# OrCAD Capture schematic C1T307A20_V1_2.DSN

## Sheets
1 PwrStr-3V3-S3
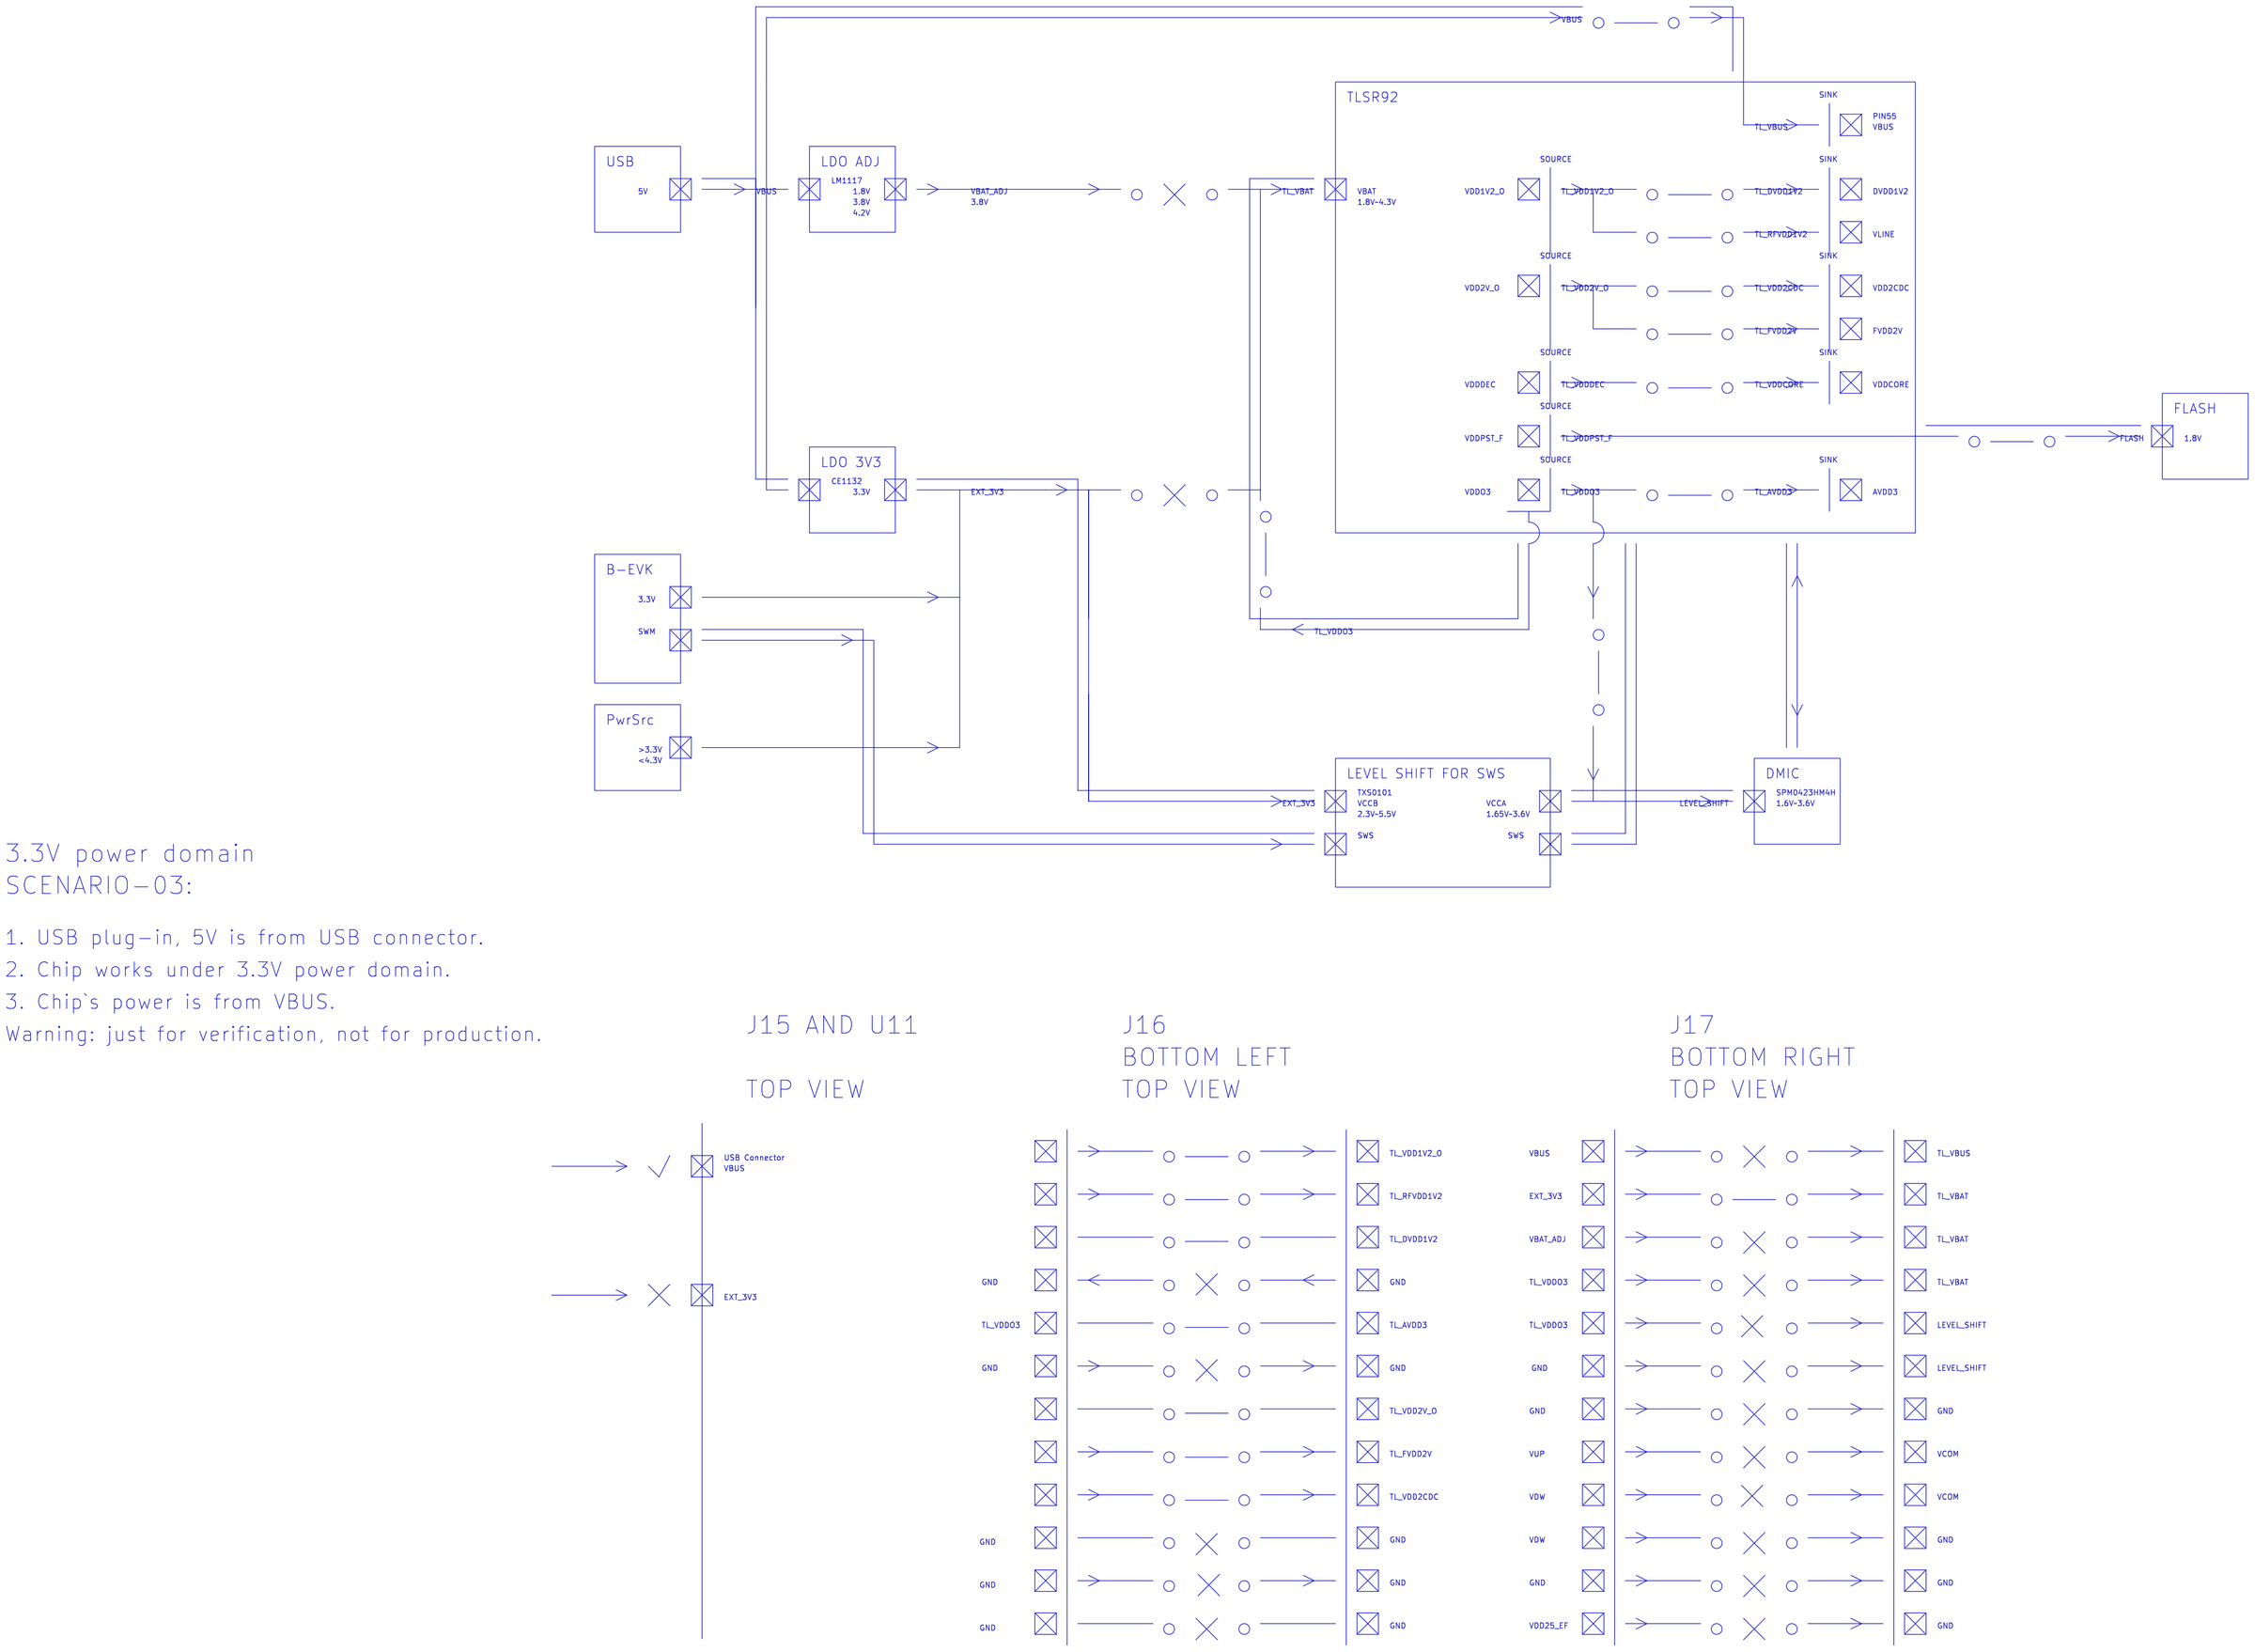
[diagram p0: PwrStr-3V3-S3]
2 PwrStr-3V3-S2
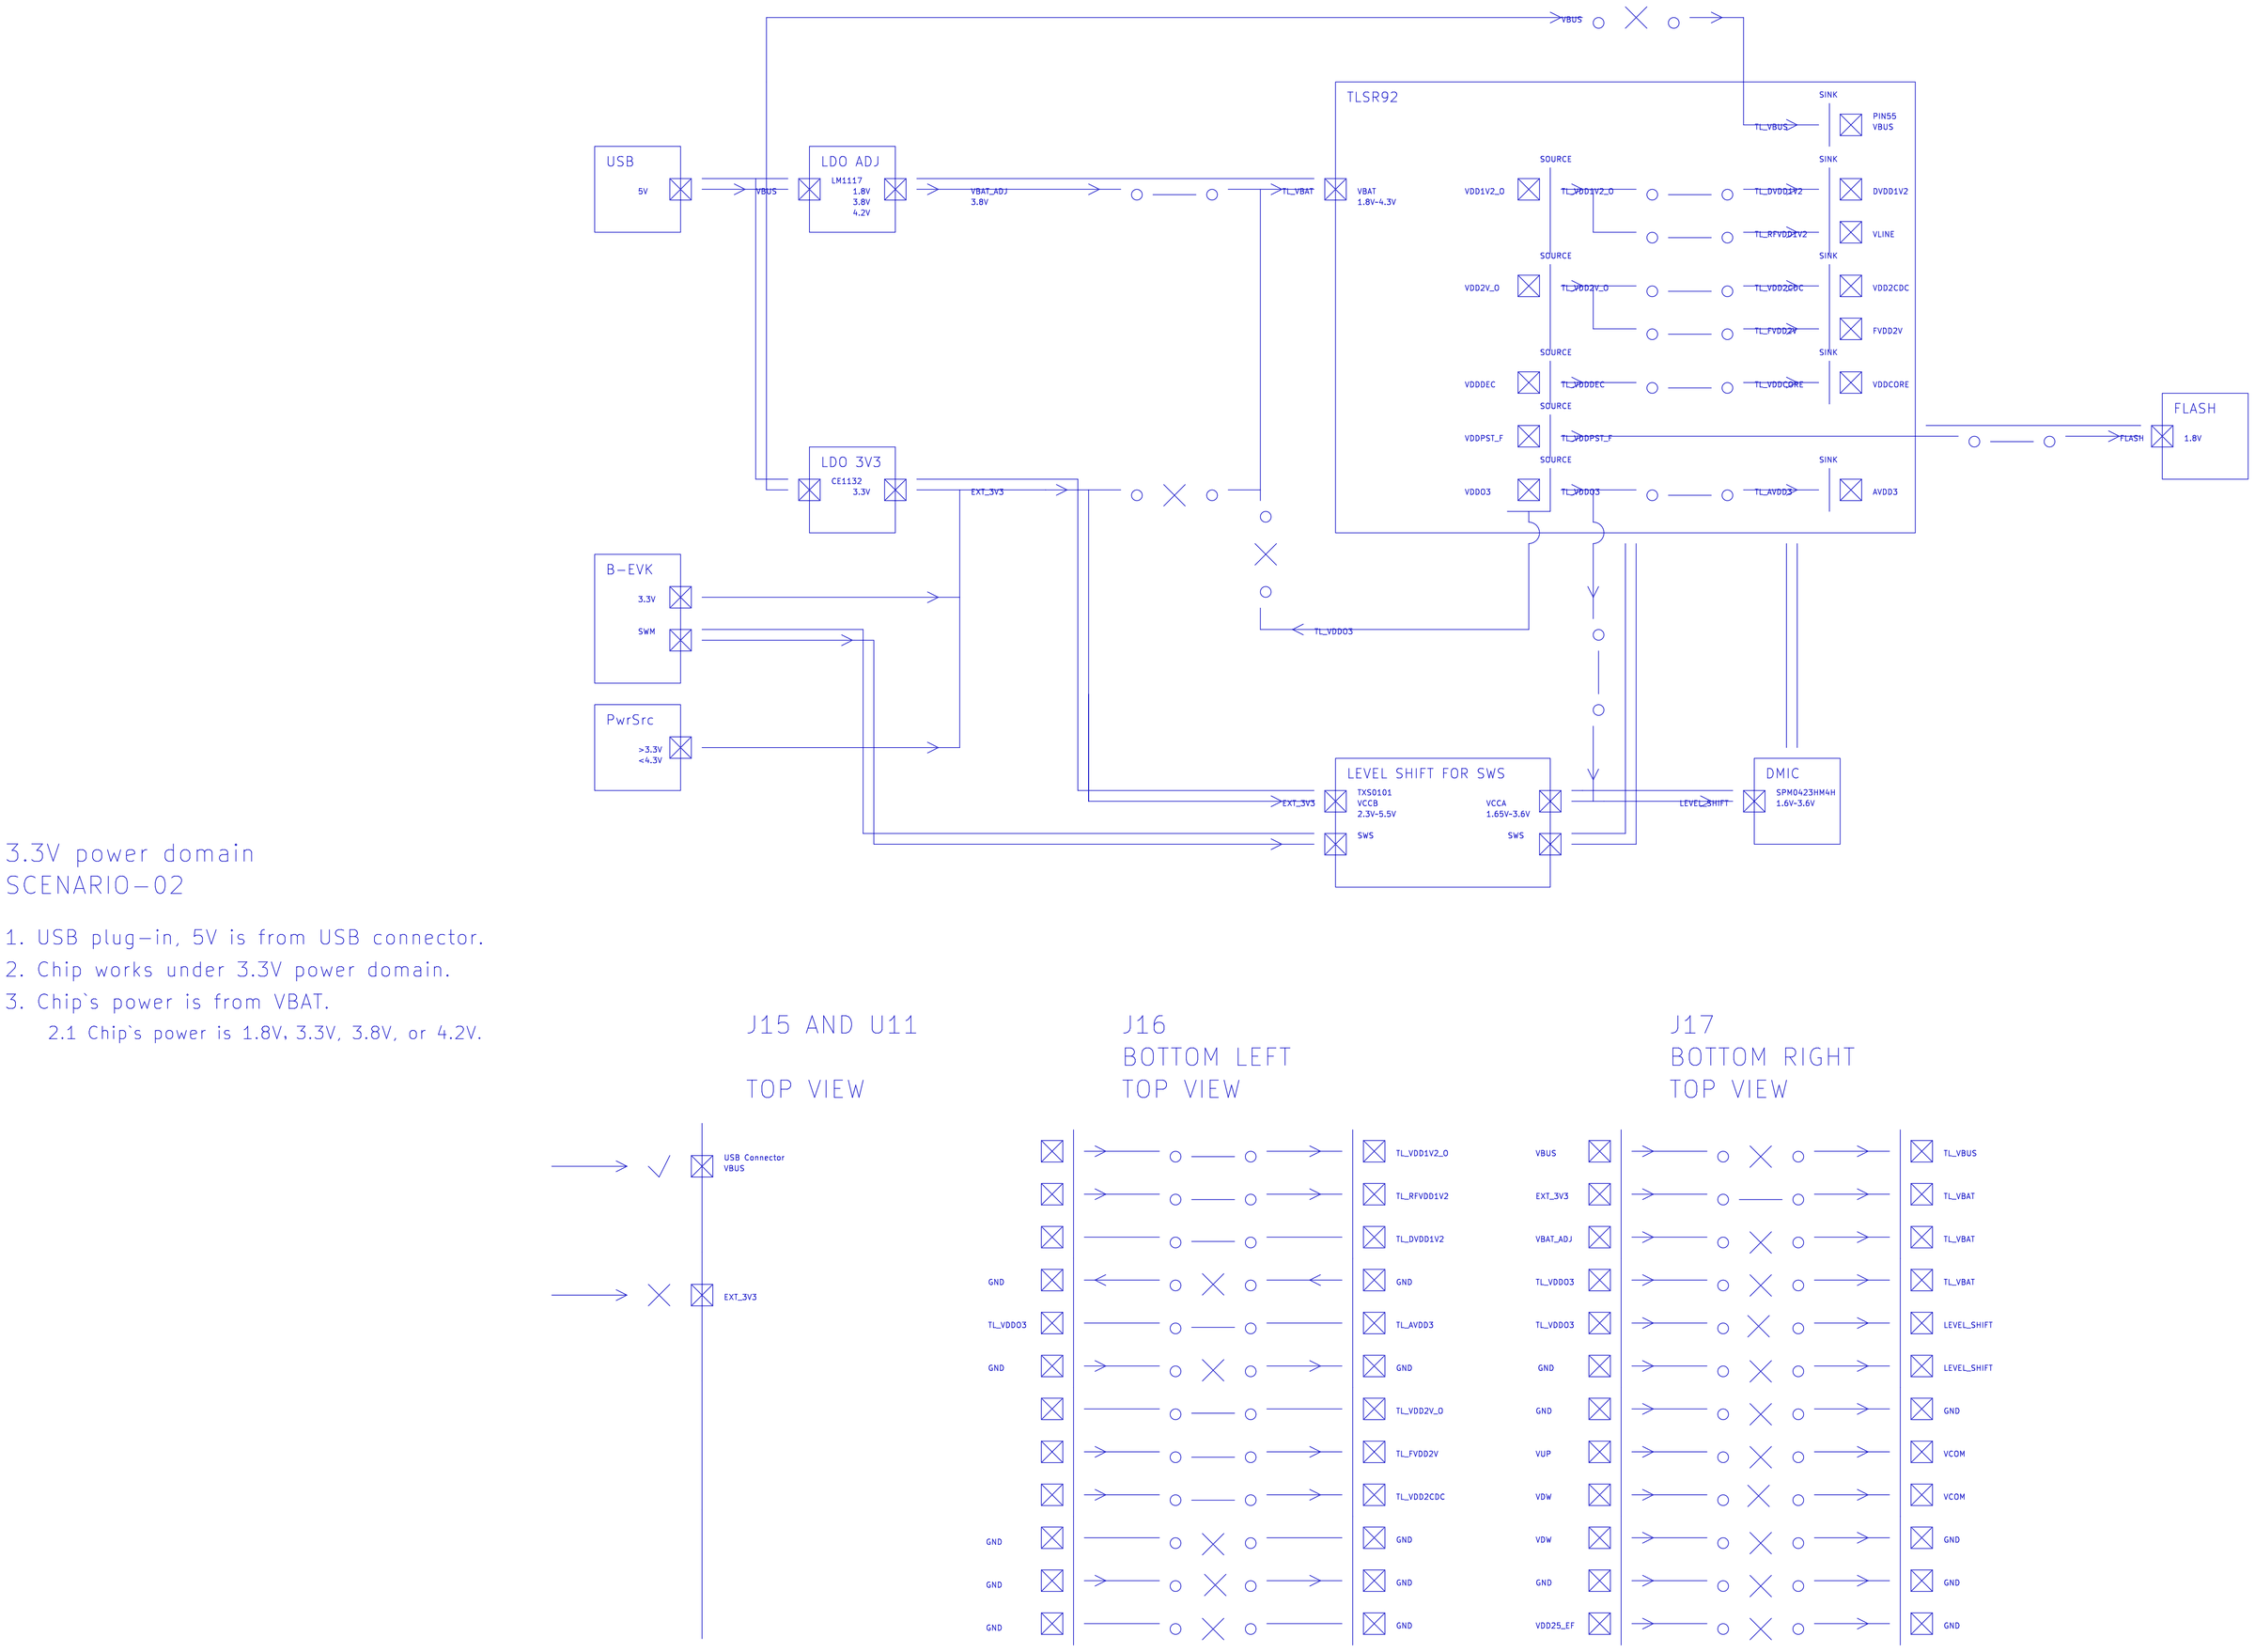
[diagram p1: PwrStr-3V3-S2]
3 PwrStr-3V3-S1
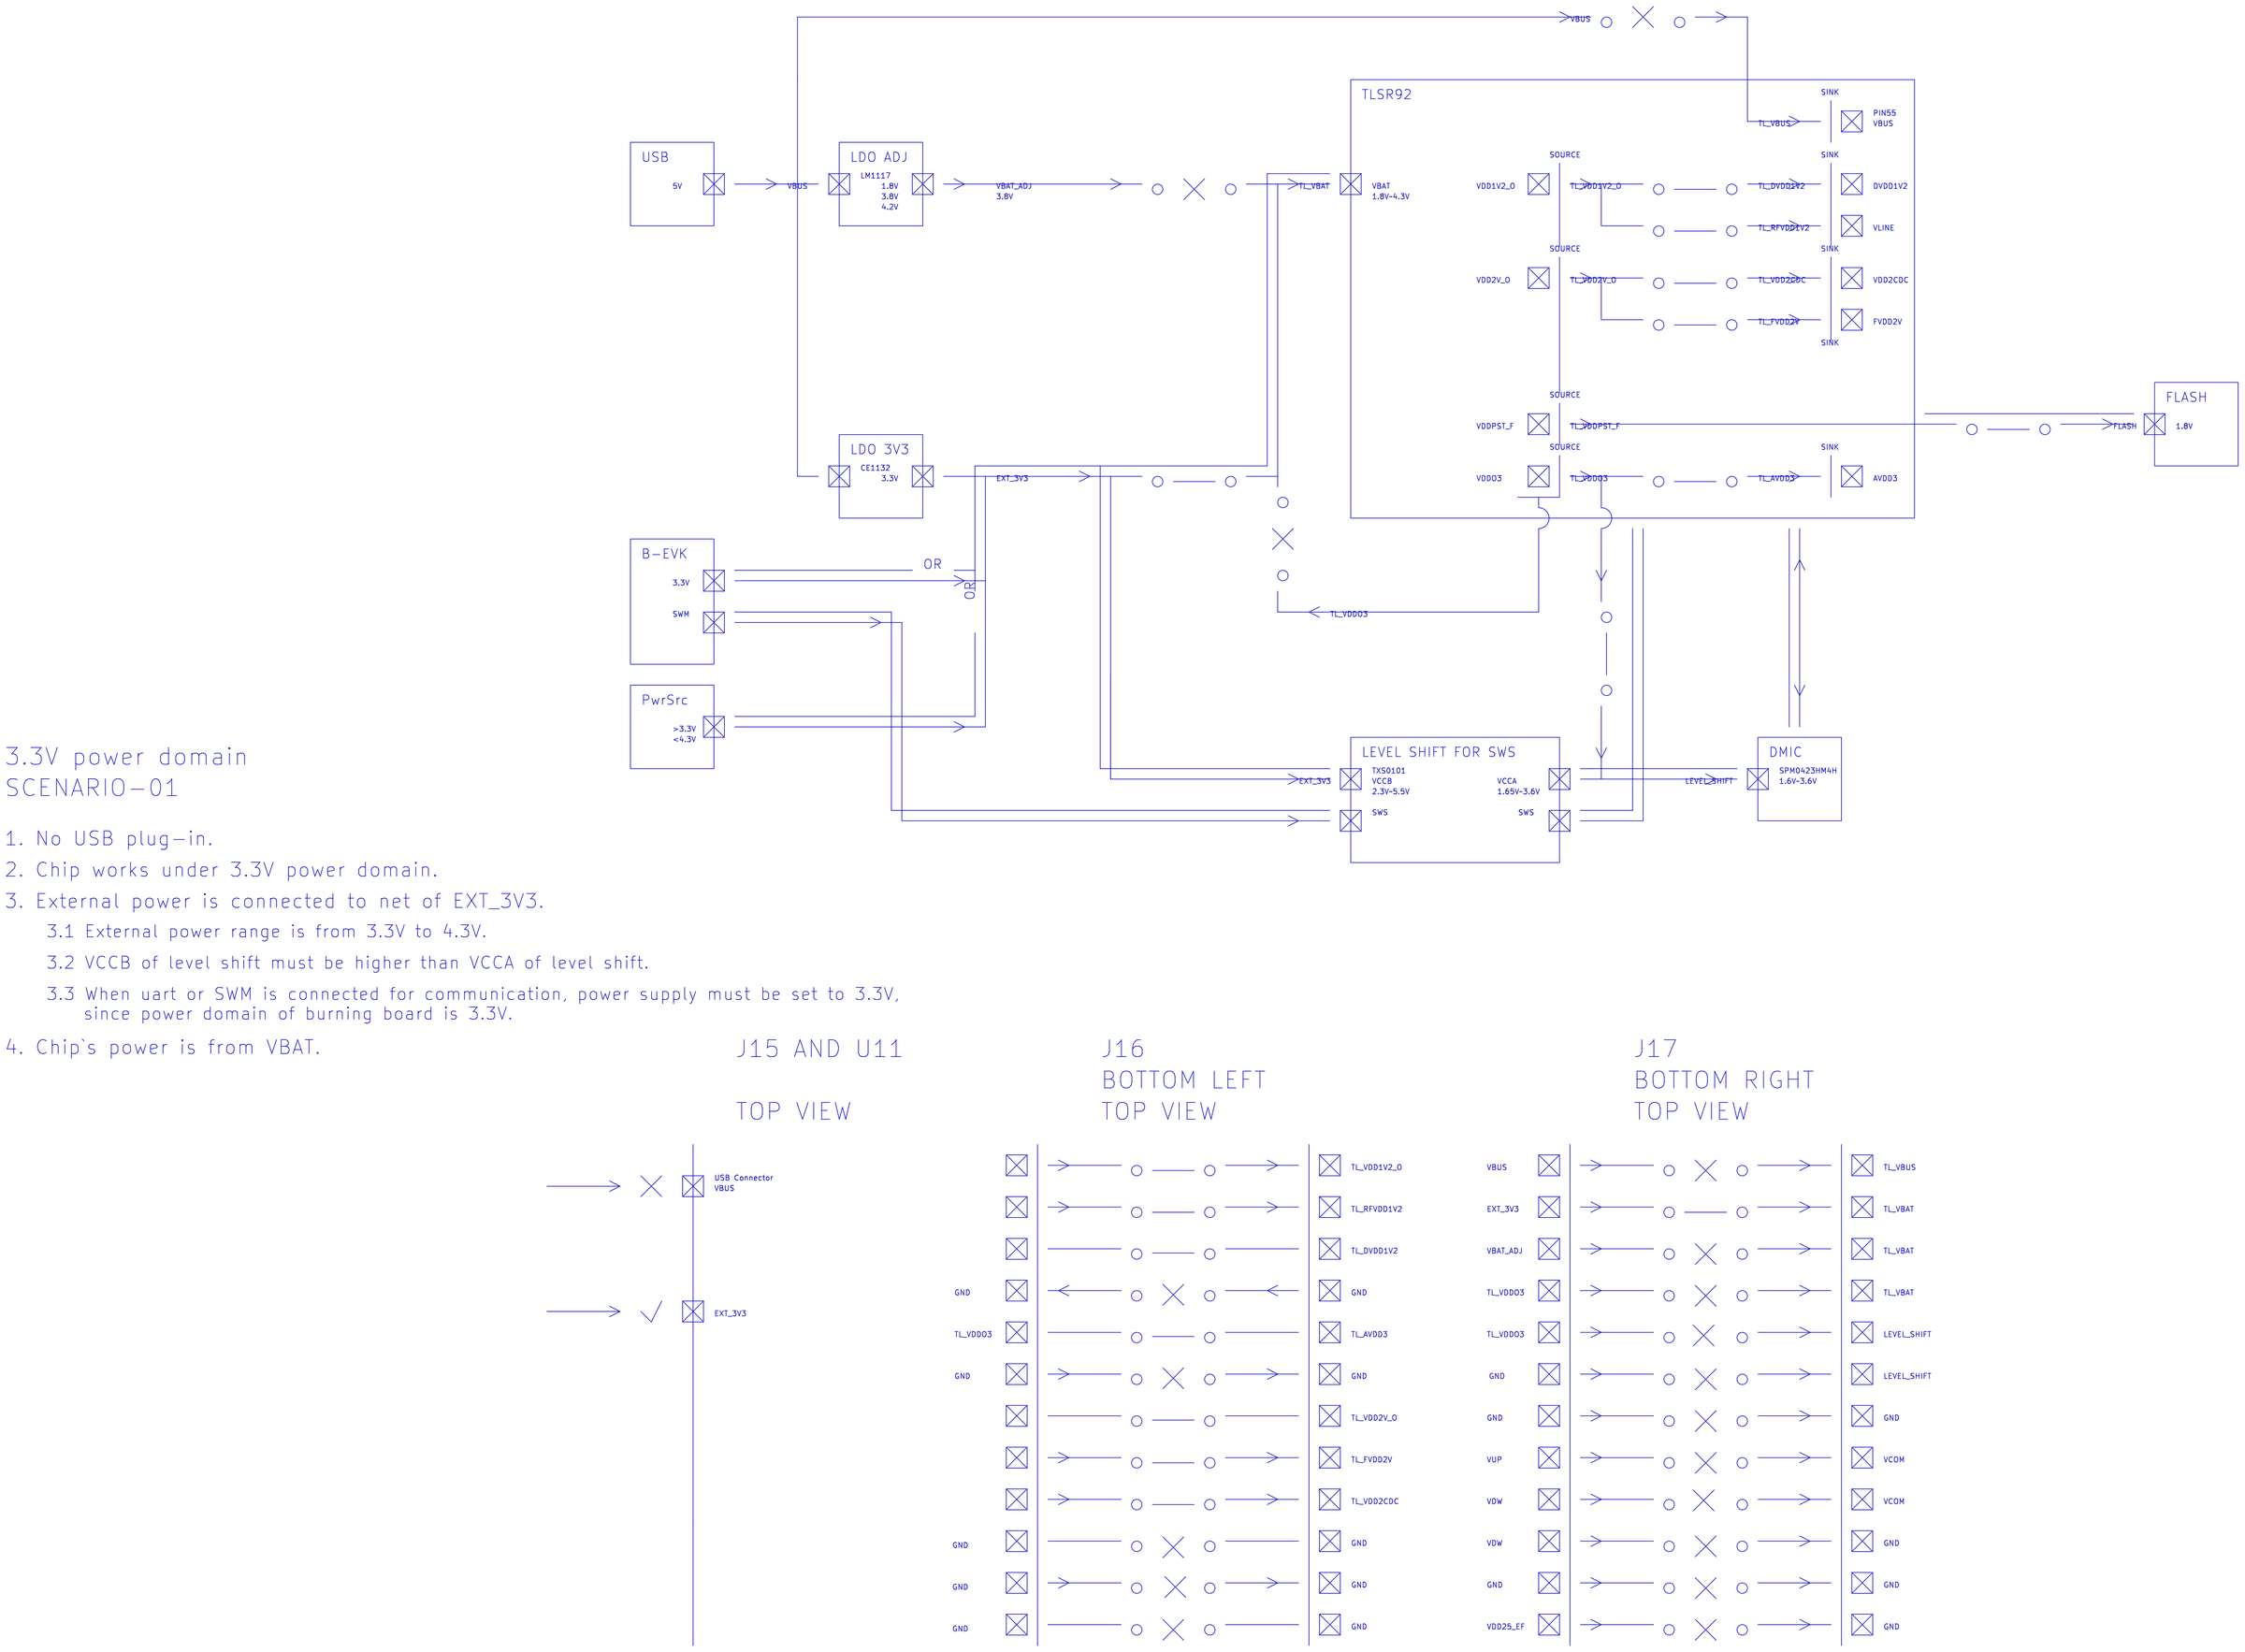
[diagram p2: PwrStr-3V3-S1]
4 000_Log: title: TELINK; rev: V1.0; note: C1T289A20
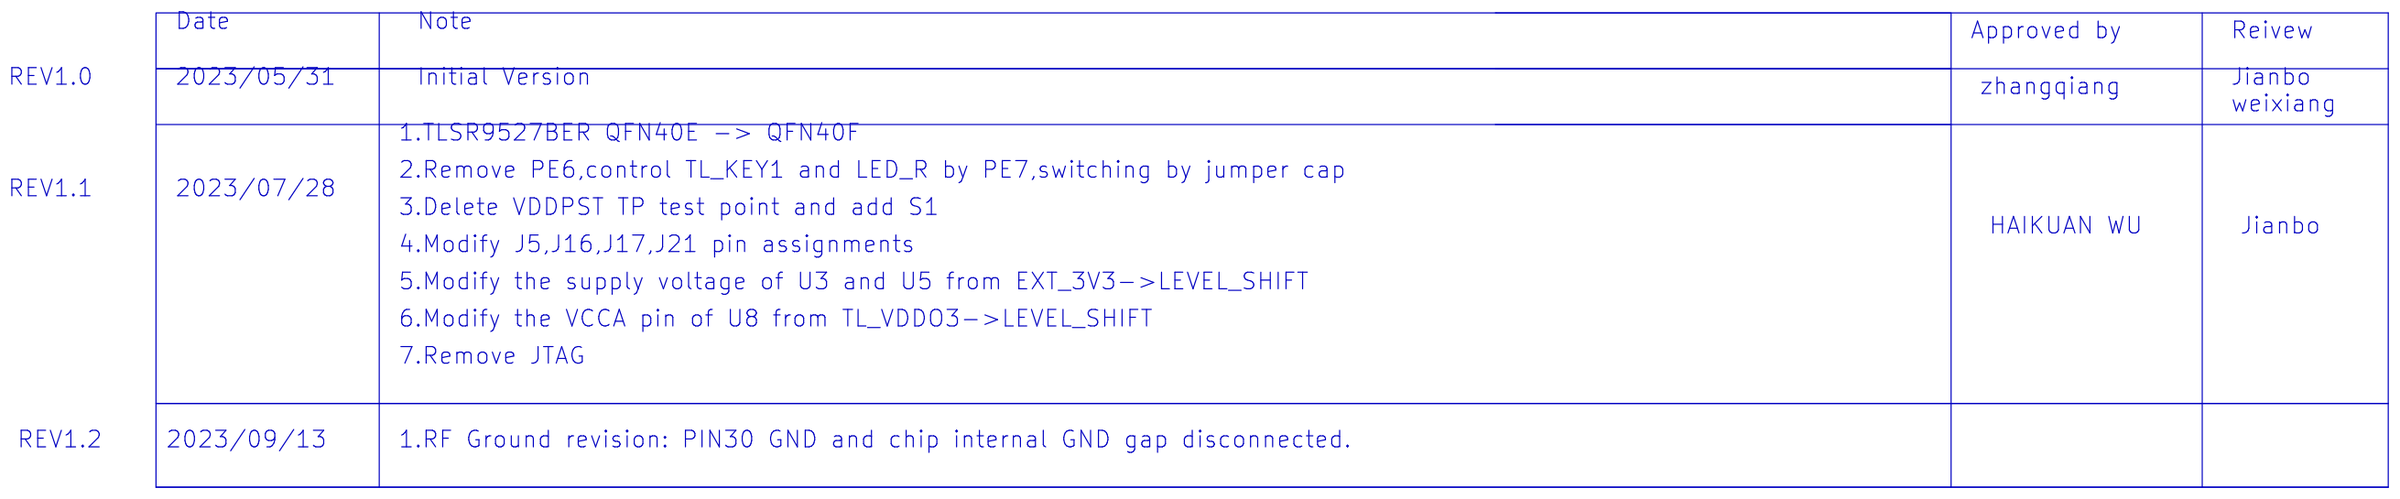
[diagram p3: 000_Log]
5 001_Structure: title: TELINK; rev: V1.1; note: C1T289A20
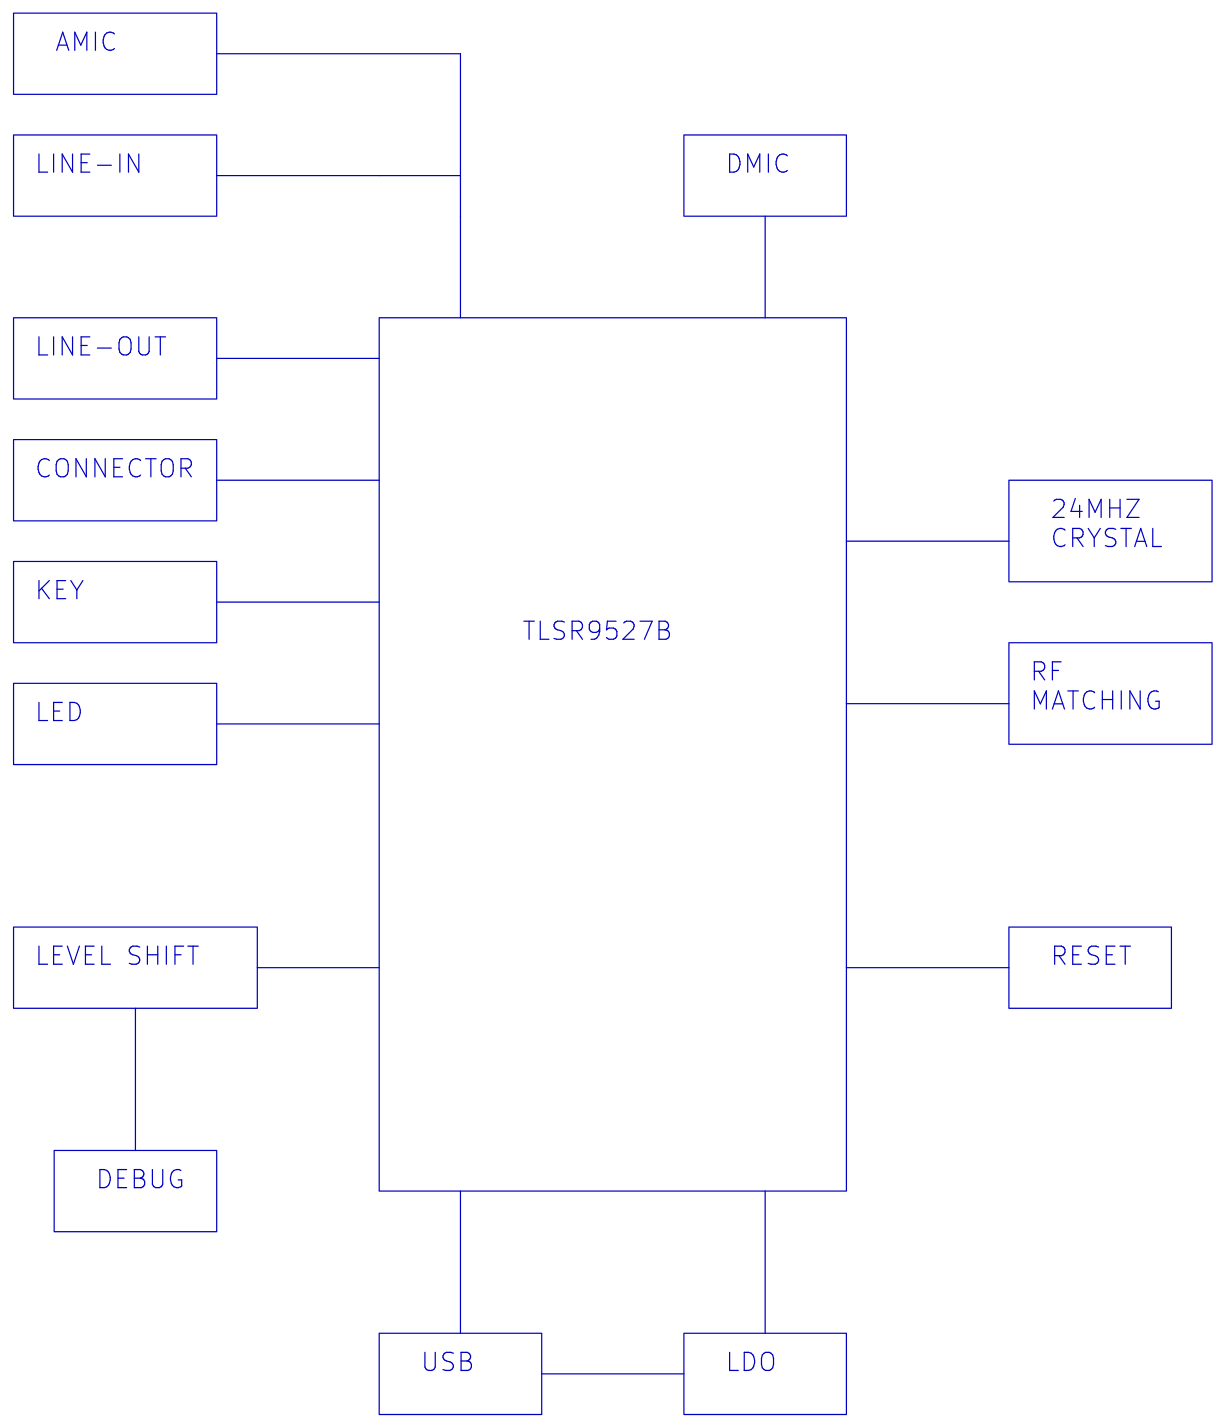
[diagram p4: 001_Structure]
6 002_MCU: size A3; title: TELINK; rev: V1.0; note: C1T289A20
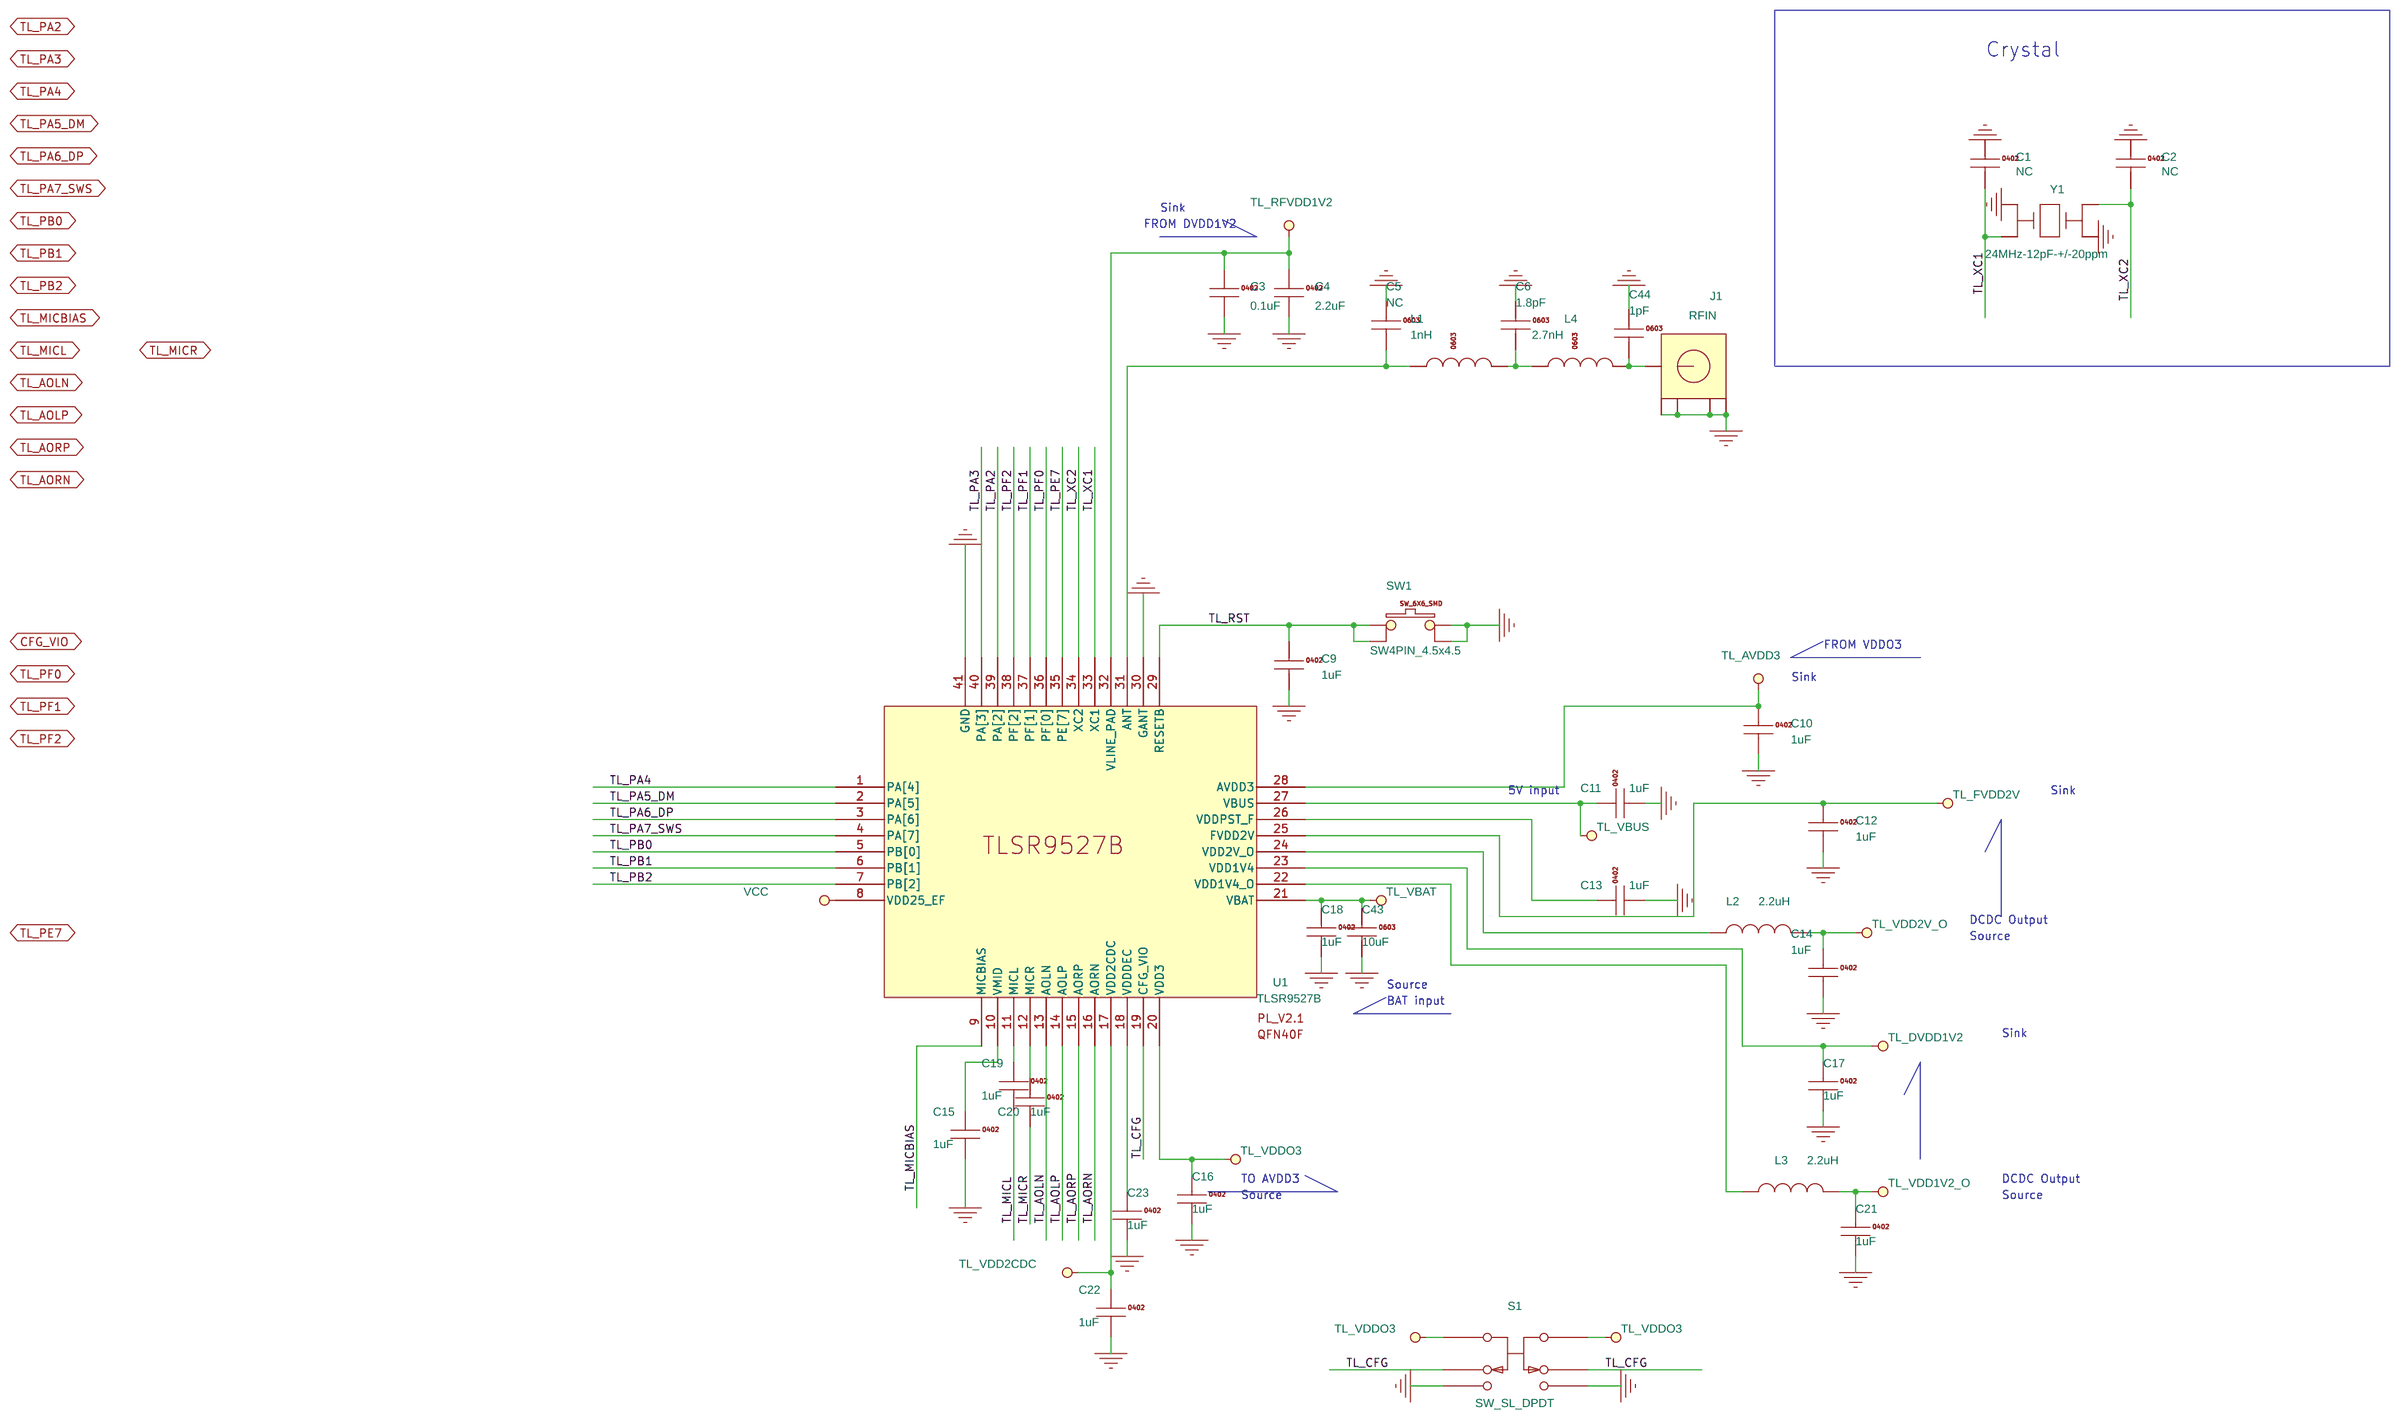
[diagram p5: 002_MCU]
7 003_INTERFACE: size A3; title: TELINK; rev: V1.0; note: C1T289A20
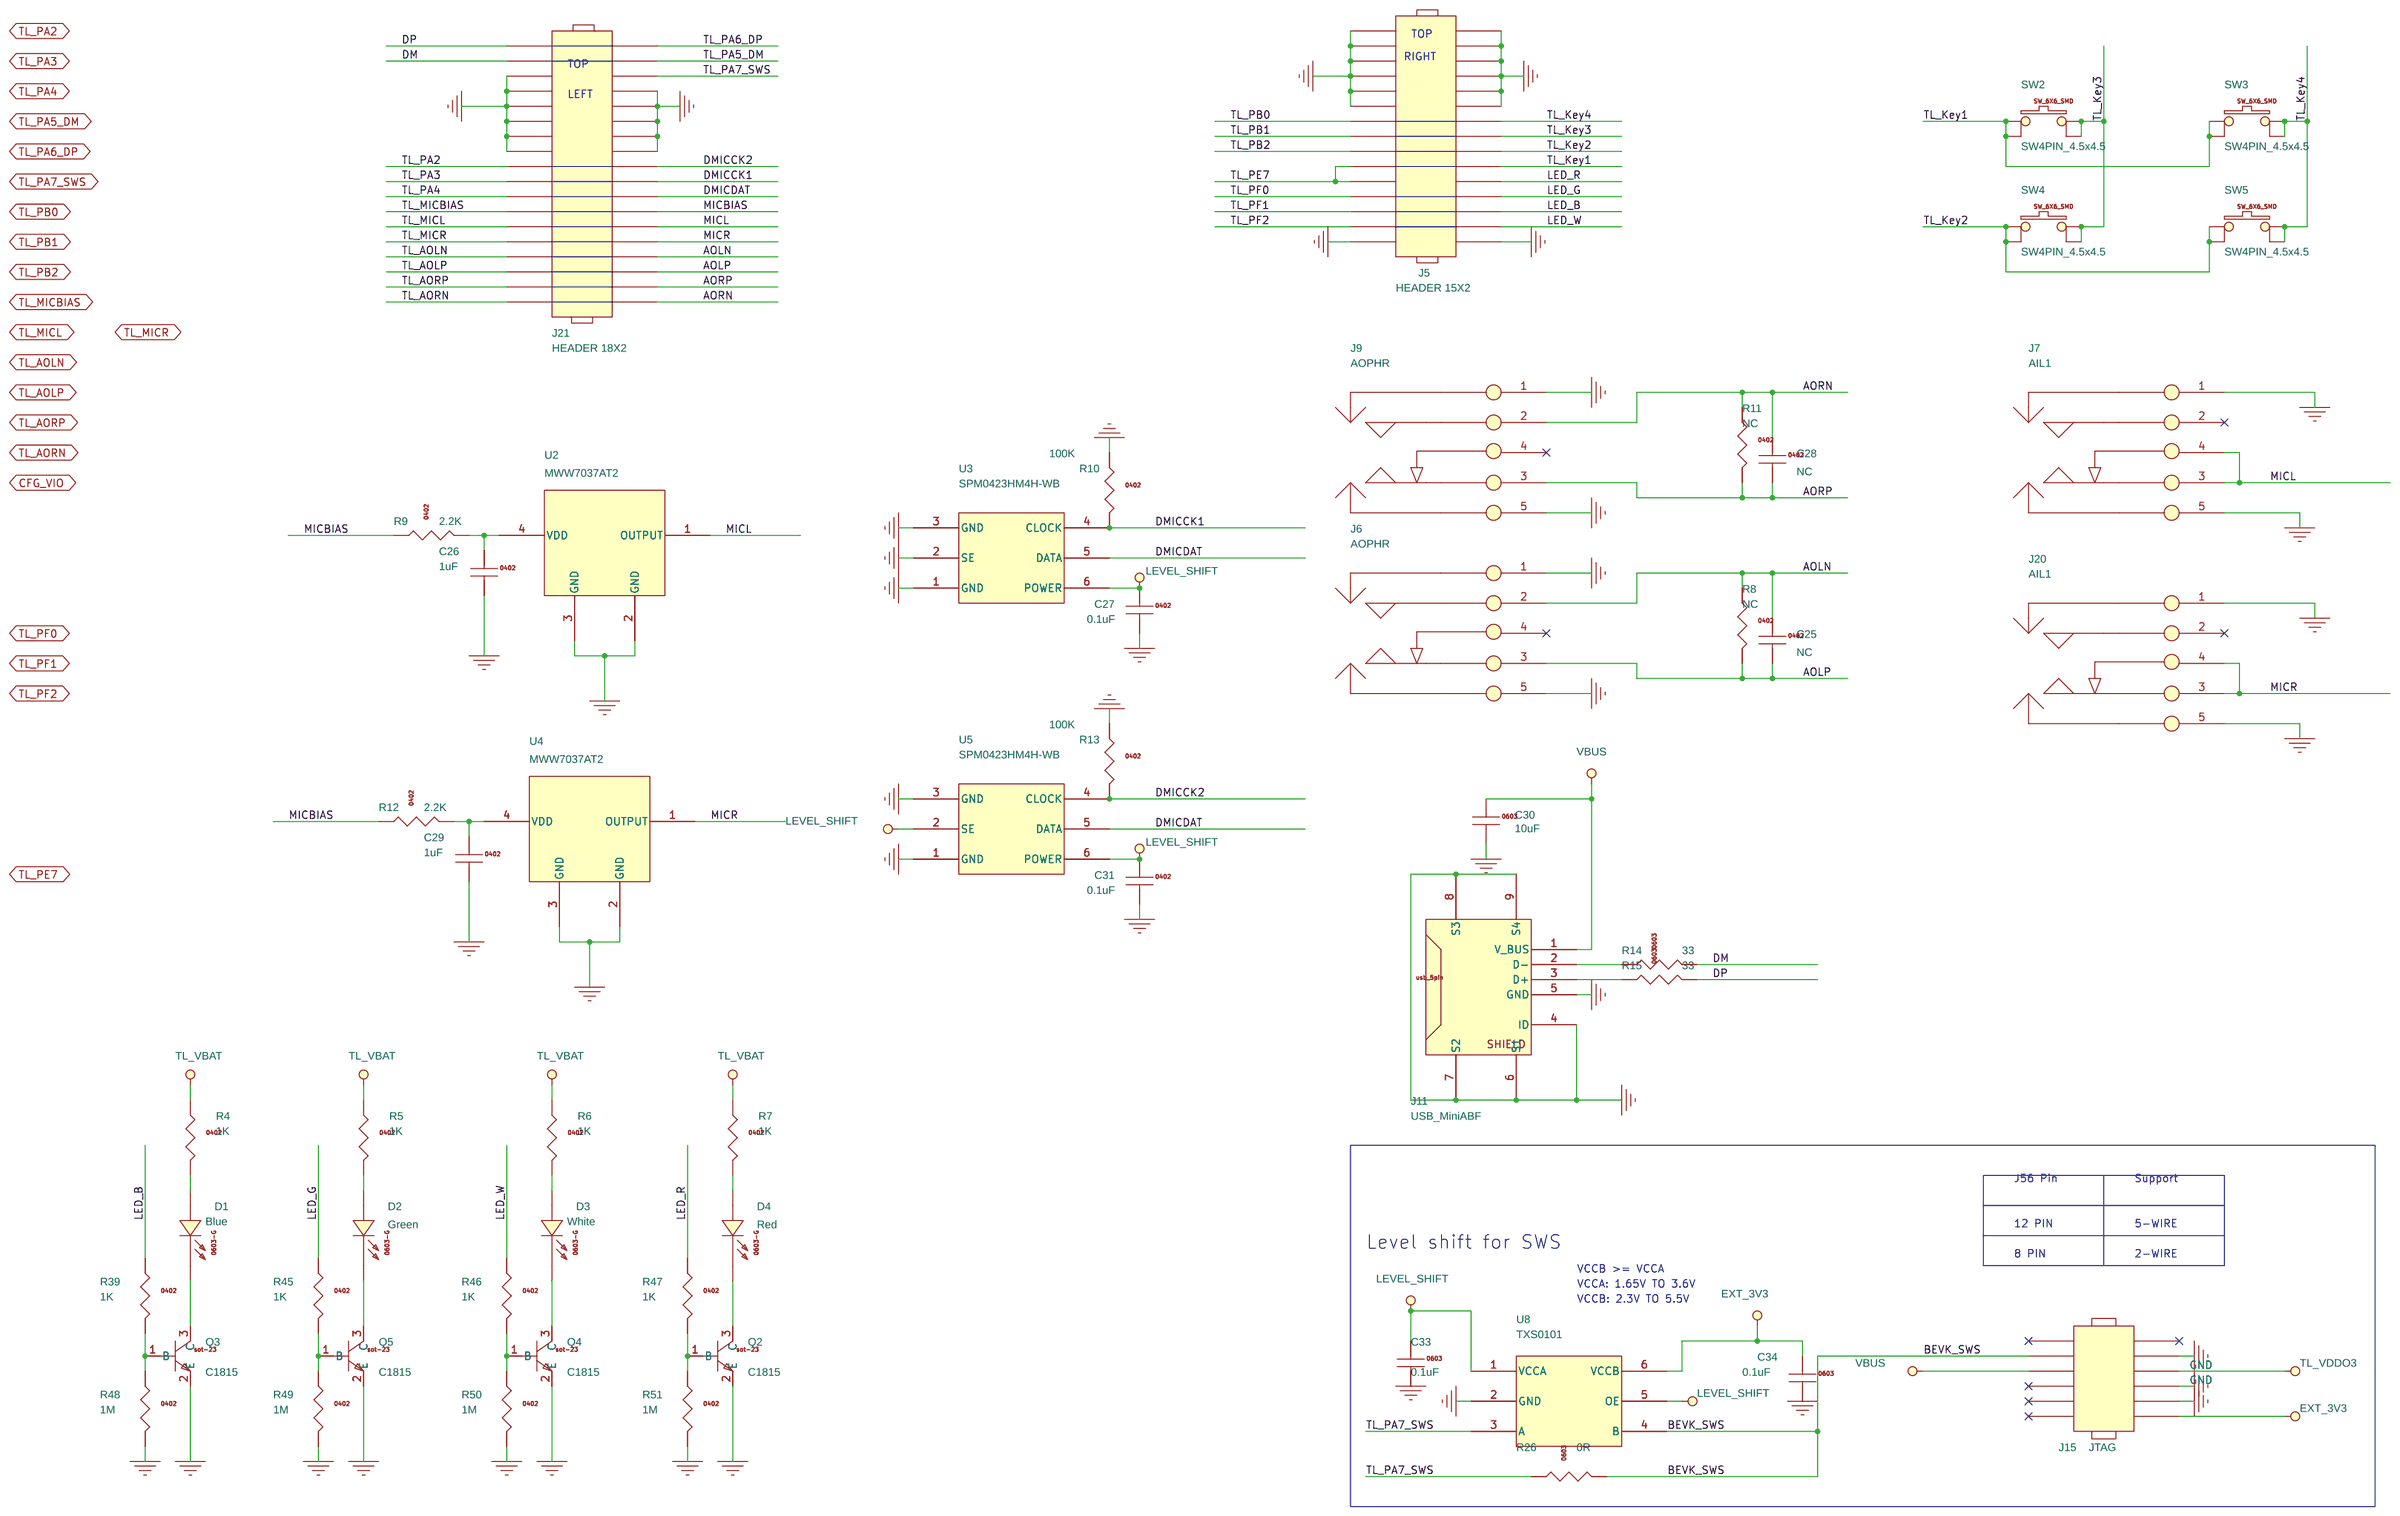
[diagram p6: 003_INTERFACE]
8 004_POWER: size A3; title: TELINK; rev: V1.0; note: C1T289A20
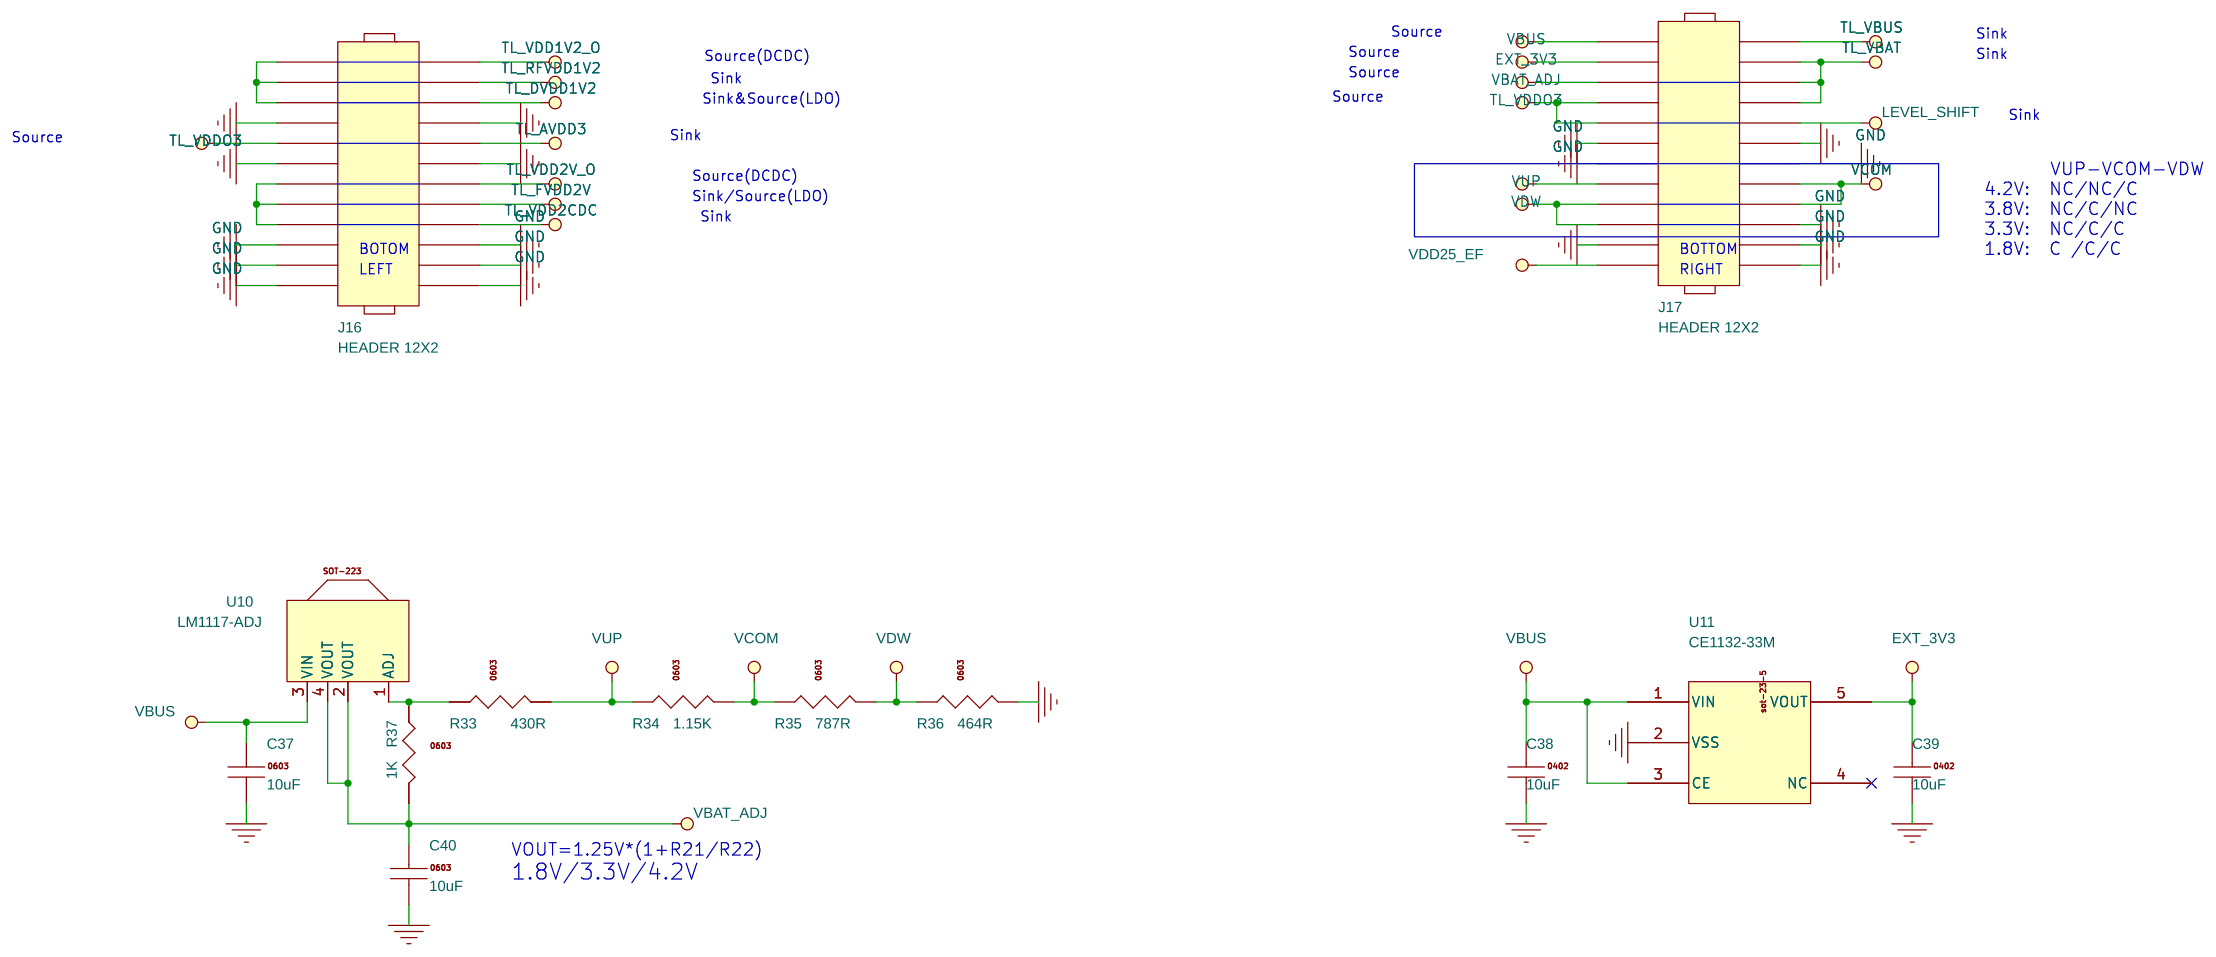
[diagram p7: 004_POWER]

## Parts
sheet 002_MCU
C1  NC  [0402]
C2  NC  [0402]
C3  0.1uF  [0402]
C4  2.2uF  [0402]
C5  NC  [0402]
C6  1.8pF  [0402]
C9  1uF  [0402]
C10  1uF  [0402]
C11  1uF  [0402]
C12  1uF  [0402]
C13  1uF  [0402]
C14  1uF  [0402]
C15  1uF  [0402]
C16  1uF  [0402]
C17  1uF  [0402]
C18  1uF  [0402]
C19  1uF  [0402]
C20  1uF  [0402]
C21  1uF  [0402]
C22  1uF  [0402]
C23  1uF  [0402]
C43  10uF  [0603C]
C44  1pF  [0402]
J1  RFIN  [SMA-H]
L1  1nH  [0402]
L2  2.2uH  [0805L]
L3  2.2uH  [0805L]
L4  2.7nH  [0402]
S1  SW_SL_DPDT  [SW-TH-6PIN-3_60X9_00-34NP]
SW1  SW4PIN_4.5x4.5  [SW_6X6_SMD]
U1  TLSR9527B  [qfn_4x6_40pin_0p4_1p10x3p10]
Y1  24MHz-12pF-+/-20ppm  [OSCCC250X320X110]
sheet 003_INTERFACE
C25  NC  [0402]
C26  1uF  [0402]
C27  0.1uF  [0402]
C28  NC  [0402]
C29  1uF  [0402]
C30  10uF  [0603C]
C31  0.1uF  [0402]
C33  0.1uF  [0402]
C34  0.1uF  [0402]
D1  Blue  [0603-LED]
D2  Green  [0603-LED]
D3  White  [0603-LED]
D4  Red  [0603-LED]
J5  HEADER 15X2  [smd254m-2x15_rx1_30y2_40]
J6  AOPHR  [PJ-327]
J7  AIL1  [PJ-327]
J9  AOPHR  [PJ-327]
J11  USB_MiniABF  [USB-MINI-F5]
J15  JTAG  [hdr254f-2x6x850]
J20  AIL1  [PJ-327]
J21  HEADER 18X2  [smd254m-2x18_rx1_30y2_40]
Q2  C1815  [SOT-23]
Q3  C1815  [SOT-23]
Q4  C1815  [SOT-23]
Q5  C1815  [SOT-23]
R4  1K  [0402]
R5  1K  [0402]
R6  1K  [0402]
R7  1K  [0402]
R8  NC  [0402]
R9  2.2K  [0402]
R10  100K  [0402]
R11  NC  [0402]
R12  2.2K  [0402]
R13  100K  [0402]
R14  33  [0402R]
R15  33  [0402R]
R26  0R  [0402R]
R39  1K  [0402]
R45  1K  [0402]
R46  1K  [0402]
R47  1K  [0402]
R48  1M  [0402]
R49  1M  [0402]
R50  1M  [0402]
R51  1M  [0402]
SW2  SW4PIN_4.5x4.5  [SW_6X6_SMD]
SW3  SW4PIN_4.5x4.5  [SW_6X6_SMD]
SW4  SW4PIN_4.5x4.5  [SW_6X6_SMD]
SW5  SW4PIN_4.5x4.5  [SW_6X6_SMD]
U2  MWW7037AT2  [ga_bfa423_a83]
U3  SPM0423HM4H-WB  [DMIC_SPM0423HM4H-WB]
U4  MWW7037AT2  [ga_bfa423_a83]
U5  SPM0423HM4H-WB  [DMIC_SPM0423HM4H-WB]
U8  TXS0101  [sc70-6]
sheet 004_POWER
C37  10uF  [0603c]
C38  10uF  [0603C]
C39  10uF  [0603C]
C40  10uF  [0603C]
J16  HEADER 12X2  [smd254m-2x12_rx1_30y2_40]
J17  HEADER 12X2  [smd254m-2x12_rx1_30y2_40]
R33  430R  [0402]
R34  1.15K  [0402]
R35  787R  [0402]
R36  464R  [0402]
R37  1K  [0402]
U10  LM1117-ADJ  [sot-223]
U11  CE1132-33M  [sot-23-5]

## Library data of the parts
C1 C2 = C1005_NC
C3 C4 C9-C23 C26 C27 C29 C31 C38 C39 = C1005X5R1C104K
C5 C6 C44 = C1608_NC
C43 = C1005X5R1C104K_0
J1 = SMA_JACK_2: PART: RF
L1 L4 = MLK1608_000R
L2 L3 = IND
S1 = SW_SL_DPDT
SW1-SW5 = SW_6X6_SMD_0
U1 = TLSR9527B
Y1 = CRYSTAL4_SM_0
C25 C28 = C1005X5R1C105K
C30 C37 = C1608X5R0J106M
C33 C34 C40 = C1608X5R1C105M
D1-D4 = 0603D_Green
J5 = HEADER_15X2
J6 J7 J9 J20 = PJ327_2
J11 = USB_MiniABF_5pin
J15 = HEADER_6X2
J21 = HEADER_18X2
Q2-Q5 = NPN_C1815
R4-R7 = RS0402K102JT
R8-R13 = RS0402K104JT
R14 R15 = RS0603K330JT
R26 = RS0603K102JT
R39 R45-R51 = RS0402K101JT
U2 U4 = MULPS4CX-RM5_0
U3 U5 = LD1117_SO_0
U8 = TXS0101
J16 J17 = HEADER_12X2
R33-R37 = RS0603K104JT
U10 = XC62FP3302_0.3V_SOT-89
U11 = XC6219_6.3V_SOT-23-5

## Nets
GND: C1.1 C2.1 C3.2 C4.2 C5.1 C6.1 C9.2 C10.2 C11.2 C12.2 C13.2 C14.2 C15.2 C16.2 C17.2 C18.2 C21.2 C22.2 C23.2 C26.2 C27.2 C29.2 C30.2 C31.2 C33.2 C34.2 C37.2 C38.2 C39.2 C40.2 C43.2 C44.1 J1.2 J1.3 J1.4 J1.5 J5.1 J5.2 J5.3 J5.4 J5.5 J5.6 J5.7 J5.8 J5.9 J5.10 J5.11 J5.12 J5.29 J5.30 J6.1 J6.5 J7.1 J7.5 J9.1 J9.5 J11.4(ID) J11.5(GND) J11.6(S1) J11.7(S2) J11.8(S3) J11.9(S4) J15.3 J15.5 J15.9 J16.7 J16.8 J16.11 J16.12 J16.19 J16.20 J16.21 J16.22 J16.23 J16.24 J17.11 J17.12 J17.13 J17.14 J17.19 J17.21 J17.22 J17.23 J20.1 J20.5 J21.6 J21.7 J21.8 J21.9 J21.10 J21.11 J21.12 J21.13 J21.14 J21.15 J21.16 Q2.2(E) Q3.2(E) Q4.2(E) Q5.2(E) R10.1 R13.1 R36.2 R48.2 R49.2 R50.2 R51.2 S1.3 S1.4 SW1.3 SW1.4 U1.30(GANT) U1.41(GND) U2.2(GND) U2.3(GND) U3.1(GND) U3.2(SE) U3.3(GND) U4.2(GND) U4.3(GND) U5.1(GND) U5.3(GND) U8.2(GND) U11.2(VSS) Y1.2 Y1.4
VBAT_ADJ: C40.1 J17.6 R37.2 U10.2(VOUT) U10.4(VOUT)
VBUS: C30.1 C37.1 C38.1 J11.1(V_BUS) J15.8 J17.2 U10.3(VIN) U11.1(VIN) U11.3(CE)
VDD25_EF: J17.24 U1.8(VDD25_EF)
AOLN: C25.1 J6.2 J21.29 R8.1
AOLP: C25.2 J6.3 J21.31 R8.2
AORN: C28.1 J9.2 J21.35 R11.1
AORP: C28.2 J9.3 J21.33 R11.2
BEVK_SWS: J15.10 R26.2 U8.4(B)
DM: J21.4 R14.2
DMICCK1: J21.19 R10.2 U3.4(CLOCK)
DMICCK2: J21.17 R13.2 U5.4(CLOCK)
DMICDAT: J21.21 U3.5(DATA) U5.5(DATA)
DP: J21.2 R15.2
EXT_3V3: C34.1 C39.1 J15.1 J17.4 U8.6(VCCB) U11.5(VOUT)
LED_B: J5.25 R39.1
LED_G: J5.23 R45.1
LED_R: J5.21 R47.1
LED_W: J5.27 R46.1
LEVEL_SHIFT: C27.1 C31.1 C33.1 J17.9 U3.6(POWER) U5.2(SE) U5.6(POWER) U8.1(VCCA) U8.5(OE)
MICBIAS: J21.23 R9.1 R12.1
MICL: J7.3 J7.4 J21.25 U2.1(OUTPUT)
MICR: J20.3 J20.4 J21.27 U4.1(OUTPUT)
TL_AOLN: U1.13(AOLN)
TL_AOLN (page 003_INTERFACE): J21.30
TL_AOLP: U1.14(AOLP)
TL_AOLP (page 003_INTERFACE): J21.32
TL_AORN: U1.16(AORN)
TL_AORN (page 003_INTERFACE): J21.36
TL_AORP: U1.15(AORP)
TL_AORP (page 003_INTERFACE): J21.34
TL_AVDD3: C10.1 J16.9 U1.28(AVDD3)
TL_CFG: S1.2 S1.5 U1.19(CFG_VIO)
TL_DVDD1V2: C17.1 J16.5 U1.23(VDD1V4)
TL_FVDD2V: C12.1 J16.15 U1.25(FVDD2V)
TL_Key1: J5.19 SW2.1 SW2.2 SW3.1 SW3.2
TL_Key2: J5.17 SW4.1 SW4.2 SW5.1 SW5.2
TL_Key3: J5.15 SW2.3 SW2.4 SW4.3 SW4.4
TL_Key4: J5.13 SW3.3 SW3.4 SW5.3 SW5.4
TL_MICBIAS: U1.9(MICBIAS)
TL_MICBIAS (page 003_INTERFACE): J21.24
TL_MICL: C19.2
TL_MICL (page 003_INTERFACE): J21.26
TL_MICR: C20.2
TL_MICR (page 003_INTERFACE): J21.28
TL_PA2: U1.39(PA[2])
TL_PA2 (page 003_INTERFACE): J21.18
TL_PA3: U1.40(PA[3])
TL_PA3 (page 003_INTERFACE): J21.20
TL_PA4: U1.1(PA[4])
TL_PA4 (page 003_INTERFACE): J21.22
TL_PA5_DM: U1.2(PA[5])
TL_PA5_DM (page 003_INTERFACE): J21.3
TL_PA6_DP: U1.3(PA[6])
TL_PA6_DP (page 003_INTERFACE): J21.1
TL_PA7_SWS: U1.4(PA[7])
TL_PA7_SWS (page 003_INTERFACE): J21.5 R26.1 U8.3(A)
TL_PB0: U1.5(PB[0])
TL_PB0 (page 003_INTERFACE): J5.14
TL_PB1: U1.6(PB[1])
TL_PB1 (page 003_INTERFACE): J5.16
TL_PB2: U1.7(PB[2])
TL_PB2 (page 003_INTERFACE): J5.18
TL_PE7: U1.35(PE[7])
TL_PE7 (page 003_INTERFACE): J5.20 J5.22
TL_PF0: U1.36(PF[0])
TL_PF0 (page 003_INTERFACE): J5.24
TL_PF1: U1.37(PF[1])
TL_PF1 (page 003_INTERFACE): J5.26
TL_PF2: U1.38(PF[2])
TL_PF2 (page 003_INTERFACE): J5.28
TL_RFVDD1V2: C3.1 C4.1 J16.3 U1.32(VLINE_PAD)
TL_RST: C9.1 SW1.1 SW1.2 U1.29(RESETB)
TL_VBAT: C18.1 C43.1 J17.3 J17.5 J17.7 R4.1 R5.1 R6.1 R7.1 U1.21(VBAT)
TL_VBUS: C11.1 J17.1 U1.27(VBUS)
TL_VDD1V2_O: C21.1 J16.1 L3.2
TL_VDD2CDC: C22.1 J16.17 U1.17(VDD2CDC)
TL_VDD2V_O: C14.1 J16.13 L2.2
TL_VDDO3: C16.1 J15.7 J16.10 J17.8 J17.10 S1.1 S1.6 U1.20(VDD3)
TL_XC1: C1.2 U1.33(XC1) Y1.3
TL_XC2: C2.2 U1.34(XC2) Y1.1
VCOM: J17.15 J17.17 R34.2 R35.1
VDW: J17.18 J17.20 R35.2 R36.1
VUP: J17.16 R33.2 R34.1
N20028206: R33.1 R37.1 U10.1(ADJ)
N20031278: C15.1 U1.10(VMID)
N20031514: C5.2 L1.1 U1.31(ANT)
N20035363: C26.1 R9.2 U2.4(VDD)
N20050417: J11.3(D+) R15.1
N20050429: J11.2(D-) R14.1
N20122497: L2.1 U1.24(VDD2V_O)
N20122505: L3.1 U1.22(VDD1V4_O)
N20122726: C13.1 U1.26(VDDPST_F)
N20123815: C29.1 R12.2 U4.4(VDD)
N20128470: D4.C(CATHODE) Q2.3(C)
N20128482: Q2.1(B) R47.2 R51.1
N20128486: D4.A(ANODE) R7.2
N20128502: D1.C(CATHODE) Q3.3(C)
N20128524: Q3.1(B) R39.2 R48.1
N20128528: D1.A(ANODE) R4.2
N20128530: D3.C(CATHODE) Q4.3(C)
N20128552: Q4.1(B) R46.2 R50.1
N20128556: D3.A(ANODE) R6.2
N20128560: D2.C(CATHODE) Q5.3(C)
N20128580: Q5.1(B) R45.2 R49.1
N20128584: D2.A(ANODE) R5.2
N20160217: C23.1 U1.18(VDDDEC)
N20160455: C20.1 U1.12(MICR)
N20160512: C19.1 U1.11(MICL)
N20164995: C44.2 J1.1 L4.2
N20165028: C6.2 L1.2 L4.1
N20174575: J16.2 J16.4 J16.6
N20174708: J16.14 J16.16 J16.18

Not connected (* = marked no-connect by the designer): J6 4*; J7 2*; J9 4*; J15 2* 4* 6* 11* 12*; J20 2*; U11 4(NC)*

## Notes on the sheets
sheet 1
- VBUS
- TLSR92
- SINK
- TL_VBUS
- PIN55
- VBUS
- USB
- LDO ADJ
- SOURCE
- SINK
- 5V
- VBUS
- LM1117
- 1.8V
- VBAT_ADJ
- TL_VBAT
- VBAT
- VDD1V2_O
- TL_VDD1V2_O
- TL_DVDD1V2
- DVDD1V2
- 3.8V
- 3.8V
- 1.8V~4.3V
- 4.2V
- TL_RFVDD1V2
- VLINE
- SOURCE
- SINK
- VDD2V_O
- TL_VDD2V_O
- TL_VDD2CDC
- VDD2CDC
- TL_FVDD2V
- FVDD2V
- SOURCE
- SINK
- VDDDEC
- TL_VDDDEC
- TL_VDDCORE
- VDDCORE
- SOURCE
- FLASH
- VDDPST_F
- TL_VDDPST_F
- FLASH
- 1.8V
- LDO 3V3
- SOURCE
- SINK
- CE1132
- 3.3V
- EXT_3V3
- VDDO3
- TL_VDDO3
- TL_AVDD3
- AVDD3
- B-EVK
- 3.3V
- SWM
- TL_VDDO3
- PwrSrc
- <4.3V
- >3.3V
- LEVEL SHIFT FOR SWS
- DMIC
- TXS0101
- SPM0423HM4H
- EXT_3V3
- VCCB
- VCCA
- LEVEL_SHIFT
- 1.6V~3.6V
- 2.3V~5.5V
- 1.65V~3.6V
- SWS
- SWS
- 3.3V power domain
- SCENARIO-03:
- 1. USB plug-in, 5V is from USB connector.
- 2. Chip works under 3.3V power domain.
- 3. Chip`s power is from VBUS.
- J15 AND U11
- J16
- J17
- Warning: just for verification, not for production.
- BOTTOM LEFT
- BOTTOM RIGHT
- TOP VIEW
- TOP VIEW
- TOP VIEW
- TL_VDD1V2_O
- VBUS
- TL_VBUS
- USB Connector
- VBUS
- TL_RFVDD1V2
- EXT_3V3
- TL_VBAT
- TL_DVDD1V2
- VBAT_ADJ
- TL_VBAT
- GND
- GND
- TL_VDDO3
- TL_VBAT
- EXT_3V3
- TL_VDDO3
- TL_AVDD3
- TL_VDDO3
- LEVEL_SHIFT
- GND
- GND
- GND
- LEVEL_SHIFT
- TL_VDD2V_O
- GND
- GND
- TL_FVDD2V
- VUP
- VCOM
- TL_VDD2CDC
- VDW
- VCOM
- GND
- GND
- VDW
- GND
- GND
- GND
- GND
- GND
- GND
- GND
- VDD25_EF
- GND
sheet 2
- VBUS
- TLSR92
- SINK
- TL_VBUS
- PIN55
- VBUS
- USB
- LDO ADJ
- SOURCE
- SINK
- 5V
- VBUS
- LM1117
- 1.8V
- VBAT_ADJ
- TL_VBAT
- VBAT
- VDD1V2_O
- TL_VDD1V2_O
- TL_DVDD1V2
- DVDD1V2
- 3.8V
- 3.8V
- 1.8V~4.3V
- 4.2V
- TL_RFVDD1V2
- VLINE
- SOURCE
- SINK
- VDD2V_O
- TL_VDD2V_O
- TL_VDD2CDC
- VDD2CDC
- TL_FVDD2V
- FVDD2V
- SOURCE
- SINK
- VDDDEC
- TL_VDDDEC
- TL_VDDCORE
- VDDCORE
- SOURCE
- FLASH
- VDDPST_F
- TL_VDDPST_F
- FLASH
- 1.8V
- LDO 3V3
- SOURCE
- SINK
- CE1132
- 3.3V
- EXT_3V3
- VDDO3
- TL_VDDO3
- TL_AVDD3
- AVDD3
- B-EVK
- 3.3V
- SWM
- TL_VDDO3
- PwrSrc
- <4.3V
- >3.3V
- LEVEL SHIFT FOR SWS
- DMIC
- TXS0101
- SPM0423HM4H
- EXT_3V3
- VCCB
- VCCA
- LEVEL_SHIFT
- 1.6V~3.6V
- 2.3V~5.5V
- 1.65V~3.6V
- SWS
- SWS
- 3.3V power domain
- SCENARIO-02
- 1. USB plug-in, 5V is from USB connector.
- 2. Chip works under 3.3V power domain.
- 3. Chip`s power is from VBAT.
- J15 AND U11
- J16
- J17
- 2.1 Chip`s power is 1.8V，3.3V, 3.8V, or 4.2V.
- BOTTOM LEFT
- BOTTOM RIGHT
- TOP VIEW
- TOP VIEW
- TOP VIEW
- TL_VDD1V2_O
- VBUS
- TL_VBUS
- USB Connector
- VBUS
- TL_RFVDD1V2
- EXT_3V3
- TL_VBAT
- TL_DVDD1V2
- VBAT_ADJ
- TL_VBAT
- GND
- GND
- TL_VDDO3
- TL_VBAT
- EXT_3V3
- TL_VDDO3
- TL_AVDD3
- TL_VDDO3
- LEVEL_SHIFT
- GND
- GND
- GND
- LEVEL_SHIFT
- TL_VDD2V_O
- GND
- GND
- TL_FVDD2V
- VUP
- VCOM
- TL_VDD2CDC
- VDW
- VCOM
- GND
- GND
- VDW
- GND
- GND
- GND
- GND
- GND
- GND
- GND
- VDD25_EF
- GND
sheet 3
- VBUS
- TLSR92
- SINK
- TL_VBUS
- PIN55
- VBUS
- USB
- LDO ADJ
- SOURCE
- SINK
- 5V
- VBUS
- LM1117
- 1.8V
- VBAT_ADJ
- TL_VBAT
- VBAT
- VDD1V2_O
- TL_VDD1V2_O
- TL_DVDD1V2
- DVDD1V2
- 3.8V
- 3.8V
- 1.8V~4.3V
- 4.2V
- TL_RFVDD1V2
- VLINE
- SOURCE
- SINK
- VDD2V_O
- TL_VDD2V_O
- TL_VDD2CDC
- VDD2CDC
- TL_FVDD2V
- FVDD2V
- SINK
- SOURCE
- FLASH
- VDDPST_F
- TL_VDDPST_F
- FLASH
- 1.8V
- LDO 3V3
- SOURCE
- SINK
- CE1132
- 3.3V
- EXT_3V3
- VDDO3
- TL_VDDO3
- TL_AVDD3
- AVDD3
- B-EVK
- OR
- 3.3V
- OR
- SWM
- TL_VDDO3
- PwrSrc
- <4.3V
- >3.3V
- 3.3V power domain
- LEVEL SHIFT FOR SWS
- DMIC
- TXS0101
- SPM0423HM4H
- SCENARIO-01
- EXT_3V3
- VCCB
- VCCA
- LEVEL_SHIFT
- 1.6V~3.6V
- 2.3V~5.5V
- 1.65V~3.6V
- SWS
- SWS
- 1. No USB plug-in.
- 2. Chip works under 3.3V power domain.
- 3. External power is connected to net of EXT_3V3.
- 3.1 External power range is from 3.3V to 4.3V.
- 3.2 VCCB of level shift must be higher than VCCA of level shift.
- 3.3 When uart or SWM is connected for communication, power supply must be set to 3.3V,
      since power domain of burning board is 3.3V.
- 4. Chip`s power is from VBAT.
- J15 AND U11
- J16
- J17
- BOTTOM LEFT
- BOTTOM RIGHT
- TOP VIEW
- TOP VIEW
- TOP VIEW
- TL_VDD1V2_O
- VBUS
- TL_VBUS
- USB Connector
- VBUS
- TL_RFVDD1V2
- EXT_3V3
- TL_VBAT
- TL_DVDD1V2
- VBAT_ADJ
- TL_VBAT
- GND
- GND
- TL_VDDO3
- TL_VBAT
- EXT_3V3
- TL_VDDO3
- TL_AVDD3
- TL_VDDO3
- LEVEL_SHIFT
- GND
- GND
- GND
- LEVEL_SHIFT
- TL_VDD2V_O
- GND
- GND
- TL_FVDD2V
- VUP
- VCOM
- TL_VDD2CDC
- VDW
- VCOM
- GND
- GND
- VDW
- GND
- GND
- GND
- GND
- GND
- GND
- GND
- VDD25_EF
- GND
sheet 4
- Date
- Note
- Approved by
- Reivew
- REV1.0
- 2023/05/31
- Initial Version
- zhangqiang
- Jianbo
  weixiang
- 1.TLSR9527BER QFN40E -> QFN40F
- 2.Remove PE6,control TL_KEY1 and LED_R by PE7,switching by jumper cap
- REV1.1
- 2023/07/28
- 3.Delete VDDPST TP test point and add S1
- HAIKUAN WU
- Jianbo
- 4.Modify J5,J16,J17,J21 pin assignments
- 5.Modify the supply voltage of U3 and U5 from EXT_3V3->LEVEL_SHIFT
- 6.Modify the VCCA pin of U8 from TL_VDDO3->LEVEL_SHIFT
- 7.Remove JTAG
- REV1.2
- 2023/09/13
- 1.RF Ground revision: PIN30 GND and chip internal GND gap disconnected.
sheet 5
- AMIC
- LINE-IN
- DMIC
- LINE-OUT
- CONNECTOR
- 24MHZ
  CRYSTAL
- KEY
- TLSR9527B
- RF
  MATCHING
- LED
- LEVEL SHIFT
- RESET
- DEBUG
- USB
- LDO
sheet 6
- Crystal
- Sink
- FROM DVDD1V2
- FROM VDDO3
- Sink
- 5V input
- Sink
- DCDC Output
- Source
- Source
- BAT input
- Sink
- TO AVDD3
- DCDC Output
- Source
- Source
sheet 7
- TOP
- TOP
- RIGHT
- LEFT
- J56 Pin
- Support
- Level shift for SWS
- 12 PIN
- 5-WIRE
- 8 PIN
- 2-WIRE
- VCCB >= VCCA
- VCCA: 1.65V TO 3.6V
- VCCB: 2.3V TO 5.5V
sheet 8
- Source
- Sink
- Source(DCDC)
- Source
- Sink
- Sink
- Source
- Sink&Source(LDO)
- Source
- Source
- Sink
- Sink
- Source(DCDC)
- VUP-VCOM-VDW
  4.2V:  NC/NC/C
  3.8V:  NC/C/NC
  3.3V:  NC/C/C
  1.8V:  C /C/C
- Sink/Source(LDO)
- Sink
- BOTOM
- BOTTOM
- LEFT
- RIGHT
- VOUT=1.25V*(1+R21/R22)
- 1.8V/3.3V/4.2V
